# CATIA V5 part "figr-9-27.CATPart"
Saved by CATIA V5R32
Part number: Part1
Bounding box of the stored display mesh (mm): x -75 to 75, y -50 to 50, z 0 to 40
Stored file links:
  D:\PROJECTS\Project 2022\CATIA V5 6R 2022\Resources\Part Files\c09_catia_v5_6r2022_prt\c09_catia_v5_6r2022_prt\figr-9-27.CATPart
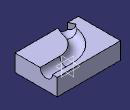
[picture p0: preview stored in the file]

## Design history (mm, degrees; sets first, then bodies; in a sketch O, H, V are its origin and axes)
Body1 (main body)
  Sketch1 on xy-plane, origin (0, 0, 0), H (1, 0, 0), V (0, 1, 0)
    line L1 (-75, 50) -> (75, 50)
    line L2 (75, 50) -> (75, -50)
    line L3 (75, -50) -> (-75, -50)
    line L4 (-75, -50) -> (-75, 50)
    axis line L5 (75, -50) -> (-75, 50)
    length L2 = 100
    length L3 = 150
    horizontal: L1 H, L3 H
    vertical: L2 V, L4 V
    midpoint: O L5
  Pad1: profile Sketch1, direction (0, 0, 1), length 40
  Sketch2 on face of Pad1, origin (75, 0, 0), H (0, 1, 0), V (0, 0, 1)
    arc A1 centre (24.1478, 40) radius 14.6047 from (9.543, 40) to (38.7525, 40) ccw
    point P1 (24.1478, 40)
    reference projected point E1 (24.1478, 40) from vertex of Sketch3
    line L1 (9.543, 40) -> (38.7525, 40)
    coincidence: P1 E1
    horizontal: L1 H
  Sketch3 on face of Pad1, origin (0, 0, 40), H (1, 0, 0), V (0, 1, 0)
    point P1 (75, 24.1478)
    line L1 (75, 24.1478) -> (28.6577, 24.1478)
    arc A1 centre (28.6577, -39.2062) radius 63.354 from (28.6577, 24.1478) to (-33.8383, -28.8149) ccw
    arc A2 centre (-62.192, -24.1005) radius 28.7429 from (-33.8383, -28.8149) to (-49.7271, -50) cw
    point P6 (-49.7271, -50)
    reference projected line E1 (75, -50) -> (75, 50) from edge [face of Pad1 | face of Pad1]
    reference projected line E2 (-75, -50) -> (75, -50) from edge [face of Pad1 | face of Pad1]
    horizontal: L1 H
    tangency: A1 L1, A2 A1
    coincidence: P1 E1, P6 E2
  Slot1: profile Sketch2, centre curve Sketch3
